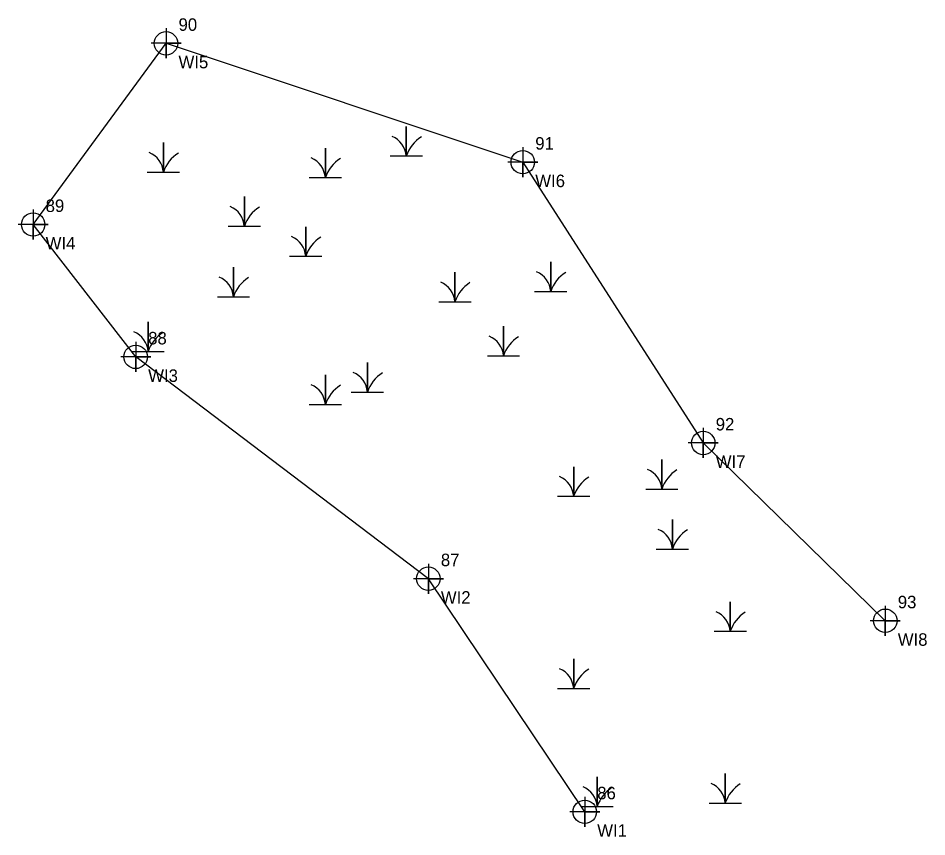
# Model space of a CAD drawing. Extents: x 2189822 to 2190837, y 387253 to 388663.
# Drawn here: x 2190002.6 to 2190184.3, y 387252.9 to 387416.7 of the extents above; entities that cross this region are included whole.
import ezdxf

# ---------------------------------------------------------------- set-up
doc = ezdxf.new("R2010")
doc.units = 0
for name, color, linetype in [('COGO Default Chain', 7, 'Continuous'), ('DTM Contours Major', 7, 'Continuous'), ('DTM Contours Minor', 7, 'Continuous'), ('Exist DTM Breakline Cogo Elevation', 7, 'Continuous'), ('Exist DTM Breakline Cogo Number', 7, 'Continuous')]:
    doc.layers.add(name, color=color, linetype=linetype)

msp = doc.modelspace()

# ---------------------------------------------------------------- linework, layer by layer
at = {"layer": 'DTM Contours Major'}
for points in [[(2190032.14, 387414.65), (2190032.14, 387408.65), (2190032.14, 387411.65), (2190035.14, 387411.65), (2190029.14, 387411.65)], [(2190103.48, 387390.89), (2190103.48, 387384.89), (2190103.48, 387387.89), (2190106.48, 387387.89), (2190100.48, 387387.89)], [(2190005.57, 387378.42), (2190005.57, 387372.42), (2190005.57, 387375.42), (2190008.57, 387375.42), (2190002.57, 387375.42)], [(2190026.07, 387351.94), (2190026.07, 387345.94), (2190026.07, 387348.94), (2190029.07, 387348.94), (2190023.07, 387348.94)], [(2190139.57, 387334.72), (2190139.57, 387328.72), (2190139.57, 387331.72), (2190142.57, 387331.72), (2190136.57, 387331.72)], [(2190084.6, 387307.58), (2190084.6, 387301.58), (2190084.6, 387304.58), (2190087.6, 387304.58), (2190081.6, 387304.58)], [(2190175.98, 387299.16), (2190175.98, 387293.16), (2190175.98, 387296.16), (2190178.98, 387296.16), (2190172.98, 387296.16)], [(2190115.87, 387260.95), (2190115.87, 387254.95), (2190115.87, 387257.95), (2190118.87, 387257.95), (2190112.87, 387257.95)]]:
    msp.add_lwpolyline(points, dxfattribs=at)
for centre in [(2190032.14, 387411.65), (2190103.48, 387387.89), (2190005.57, 387375.42), (2190026.07, 387348.94), (2190139.57, 387331.72), (2190084.6, 387304.58), (2190175.98, 387296.16), (2190115.87, 387257.95)]:
    msp.add_circle(centre, 2.34, dxfattribs=at)
at = {"layer": 'Exist DTM Breakline Cogo Elevation'}
for p, q in [((2190080.19, 387391.79), (2190080.19, 387391.79)), ((2190031.61, 387388.55), (2190031.61, 387388.55)), ((2190064, 387387.47), (2190064, 387387.47)), ((2190047.8, 387377.75), (2190047.8, 387377.75)), ((2190060.08, 387371.74), (2190060.08, 387371.74)), ((2190109.08, 387364.69), (2190109.08, 387364.69)), ((2190045.62, 387363.63), (2190045.62, 387363.63)), ((2190089.91, 387362.62), (2190089.91, 387362.62)), ((2190028.57, 387352.69), (2190028.57, 387352.69)), ((2190099.62, 387351.82), (2190099.62, 387351.82)), ((2190072.42, 387344.58), (2190072.42, 387344.58)), ((2190064, 387342.1), (2190064, 387342.1)), ((2190131.29, 387325.18), (2190131.29, 387325.18)), ((2190113.66, 387323.73), (2190113.66, 387323.73)), ((2190133.4, 387313.18), (2190133.4, 387313.18)), ((2190144.97, 387296.73), (2190144.97, 387296.73)), ((2190113.66, 387285.32), (2190113.66, 387285.32)), ((2190118.37, 387261.7), (2190118.37, 387261.7)), ((2190143.98, 387262.39), (2190143.98, 387262.39))]:
    msp.add_line(p, q, dxfattribs=at)
for points in [[(2190076.97, 387389.12), (2190080.19, 387389.12), (2190080.19, 387395.04), (2190080.19, 387389.12), (2190083.42, 387389.12)], [(2190028.38, 387385.88), (2190031.61, 387385.88), (2190031.61, 387391.79), (2190031.61, 387385.88), (2190034.84, 387385.88)], [(2190060.77, 387384.8), (2190064, 387384.8), (2190064, 387390.71), (2190064, 387384.8), (2190067.22, 387384.8)], [(2190044.58, 387375.07), (2190047.8, 387375.07), (2190047.8, 387380.99), (2190047.8, 387375.07), (2190051.03, 387375.07)], [(2190056.85, 387369.07), (2190060.08, 387369.07), (2190060.08, 387374.98), (2190060.08, 387369.07), (2190063.3, 387369.07)], [(2190042.4, 387360.95), (2190045.62, 387360.95), (2190045.62, 387366.87), (2190045.62, 387360.95), (2190048.85, 387360.95)], [(2190105.85, 387362.01), (2190109.08, 387362.01), (2190109.08, 387367.93), (2190109.08, 387362.01), (2190112.3, 387362.01)], [(2190086.68, 387359.95), (2190089.91, 387359.95), (2190089.91, 387365.87), (2190089.91, 387359.95), (2190093.13, 387359.95)], [(2190025.34, 387350.02), (2190028.57, 387350.02), (2190028.57, 387355.93), (2190028.57, 387350.02), (2190031.79, 387350.02)], [(2190096.4, 387349.15), (2190099.63, 387349.15), (2190099.63, 387355.06), (2190099.63, 387349.15), (2190102.85, 387349.15)], [(2190069.19, 387341.9), (2190072.42, 387341.9), (2190072.42, 387347.82), (2190072.42, 387341.9), (2190075.64, 387341.9)], [(2190060.77, 387339.42), (2190064, 387339.42), (2190064, 387345.34), (2190064, 387339.42), (2190067.22, 387339.42)], [(2190128.06, 387322.5), (2190131.29, 387322.5), (2190131.29, 387328.42), (2190131.29, 387322.5), (2190134.51, 387322.5)], [(2190110.43, 387321.06), (2190113.66, 387321.06), (2190113.66, 387326.98), (2190113.66, 387321.06), (2190116.89, 387321.06)], [(2190130.18, 387310.51), (2190133.4, 387310.51), (2190133.4, 387316.43), (2190133.4, 387310.51), (2190136.63, 387310.51)], [(2190141.74, 387294.05), (2190144.97, 387294.05), (2190144.97, 387299.97), (2190144.97, 387294.05), (2190148.19, 387294.05)], [(2190110.44, 387282.64), (2190113.66, 387282.64), (2190113.66, 387288.56), (2190113.66, 387282.64), (2190116.89, 387282.64)], [(2190115.14, 387259.02), (2190118.37, 387259.02), (2190118.37, 387264.94), (2190118.37, 387259.02), (2190121.59, 387259.02)], [(2190140.75, 387259.71), (2190143.98, 387259.71), (2190143.98, 387265.63), (2190143.98, 387259.71), (2190147.2, 387259.71)]]:
    msp.add_lwpolyline(points, dxfattribs=at)
for centre, radius, start, end in [((2190075.59, 387388.78), 4.61, 4.1403, 67.535), ((2190087.03, 387386.84), 7.21, 122.1274, 161.6222), ((2190027.01, 387385.54), 4.61, 4.1403, 67.535), ((2190038.45, 387383.6), 7.21, 122.1274, 161.6222), ((2190059.4, 387384.46), 4.61, 4.1403, 67.535), ((2190070.84, 387382.52), 7.21, 122.1274, 161.6222), ((2190043.2, 387374.74), 4.61, 4.1403, 67.535), ((2190054.65, 387372.8), 7.21, 122.1274, 161.6222), ((2190055.48, 387368.73), 4.61, 4.1403, 67.535), ((2190066.92, 387366.79), 7.21, 122.1274, 161.6222), ((2190041.02, 387360.62), 4.61, 4.1403, 67.535), ((2190052.47, 387358.68), 7.21, 122.1274, 161.6222), ((2190104.48, 387361.68), 4.61, 4.1403, 67.535), ((2190115.92, 387359.74), 7.21, 122.1274, 161.6222), ((2190085.31, 387359.62), 4.61, 4.1403, 67.535), ((2190096.75, 387357.68), 7.21, 122.1274, 161.6222), ((2190023.97, 387349.68), 4.61, 4.1403, 67.535), ((2190035.41, 387347.74), 7.21, 122.1274, 161.6222), ((2190095.03, 387348.81), 4.61, 4.1403, 67.535), ((2190106.47, 387346.87), 7.21, 122.1274, 161.6222), ((2190067.82, 387341.57), 4.61, 4.1403, 67.535), ((2190079.26, 387339.63), 7.21, 122.1274, 161.6222), ((2190059.4, 387339.09), 4.61, 4.1403, 67.535), ((2190070.84, 387337.15), 7.21, 122.1274, 161.6222), ((2190126.69, 387322.17), 4.61, 4.1403, 67.535), ((2190109.06, 387320.73), 4.61, 4.1403, 67.535), ((2190120.5, 387318.79), 7.21, 122.1274, 161.6222), ((2190138.13, 387320.23), 7.21, 122.1274, 161.6222), ((2190128.8, 387310.18), 4.61, 4.1403, 67.535), ((2190140.24, 387308.24), 7.21, 122.1274, 161.6222), ((2190140.37, 387293.72), 4.61, 4.1403, 67.535), ((2190151.81, 387291.78), 7.21, 122.1274, 161.6222), ((2190109.06, 387282.31), 4.61, 4.1403, 67.535), ((2190120.5, 387280.37), 7.21, 122.1274, 161.6222), ((2190113.77, 387258.69), 4.61, 4.1403, 67.535), ((2190125.21, 387256.75), 7.21, 122.1274, 161.6222), ((2190139.38, 387259.38), 4.61, 4.1403, 67.535), ((2190150.82, 387257.44), 7.21, 122.1274, 161.6222)]:
    msp.add_arc(centre, radius, start, end, dxfattribs=at)
at = {"layer": 'Exist DTM Breakline Cogo Number'}
msp.add_lwpolyline([(2190115.87, 387257.95), (2190084.6, 387304.58), (2190026.07, 387348.94), (2190005.57, 387375.42), (2190032.14, 387411.65), (2190103.48, 387387.89), (2190139.57, 387331.72), (2190175.98, 387296.16)], dxfattribs=at)

# ---------------------------------------------------------------- texts
at = {"layer": 'COGO Default Chain'}
for s, p in [('WI5', (2190034.64, 387406.65)), ('WI6', (2190105.98, 387382.89)), ('WI4', (2190008.07, 387370.42)), ('WI3', (2190028.57, 387343.94)), ('WI7', (2190142.07, 387326.72)), ('WI2', (2190087.1, 387299.58)), ('WI8', (2190178.48, 387291.16)), ('WI1', (2190118.37, 387252.95))]:
    msp.add_text(s, height=2.5, dxfattribs=at).set_placement(p)
at = {"layer": 'DTM Contours Minor'}
for s, p in [('90', (2190034.64, 387414.15)), ('91', (2190105.98, 387390.39)), ('89', (2190008.07, 387377.92)), ('88', (2190028.57, 387351.44)), ('92', (2190142.07, 387334.22)), ('87', (2190087.1, 387307.08)), ('93', (2190178.48, 387298.66)), ('86', (2190118.37, 387260.45))]:
    msp.add_text(s, height=2.5, dxfattribs=at).set_placement(p)

doc.saveas('drawing.dxf')
